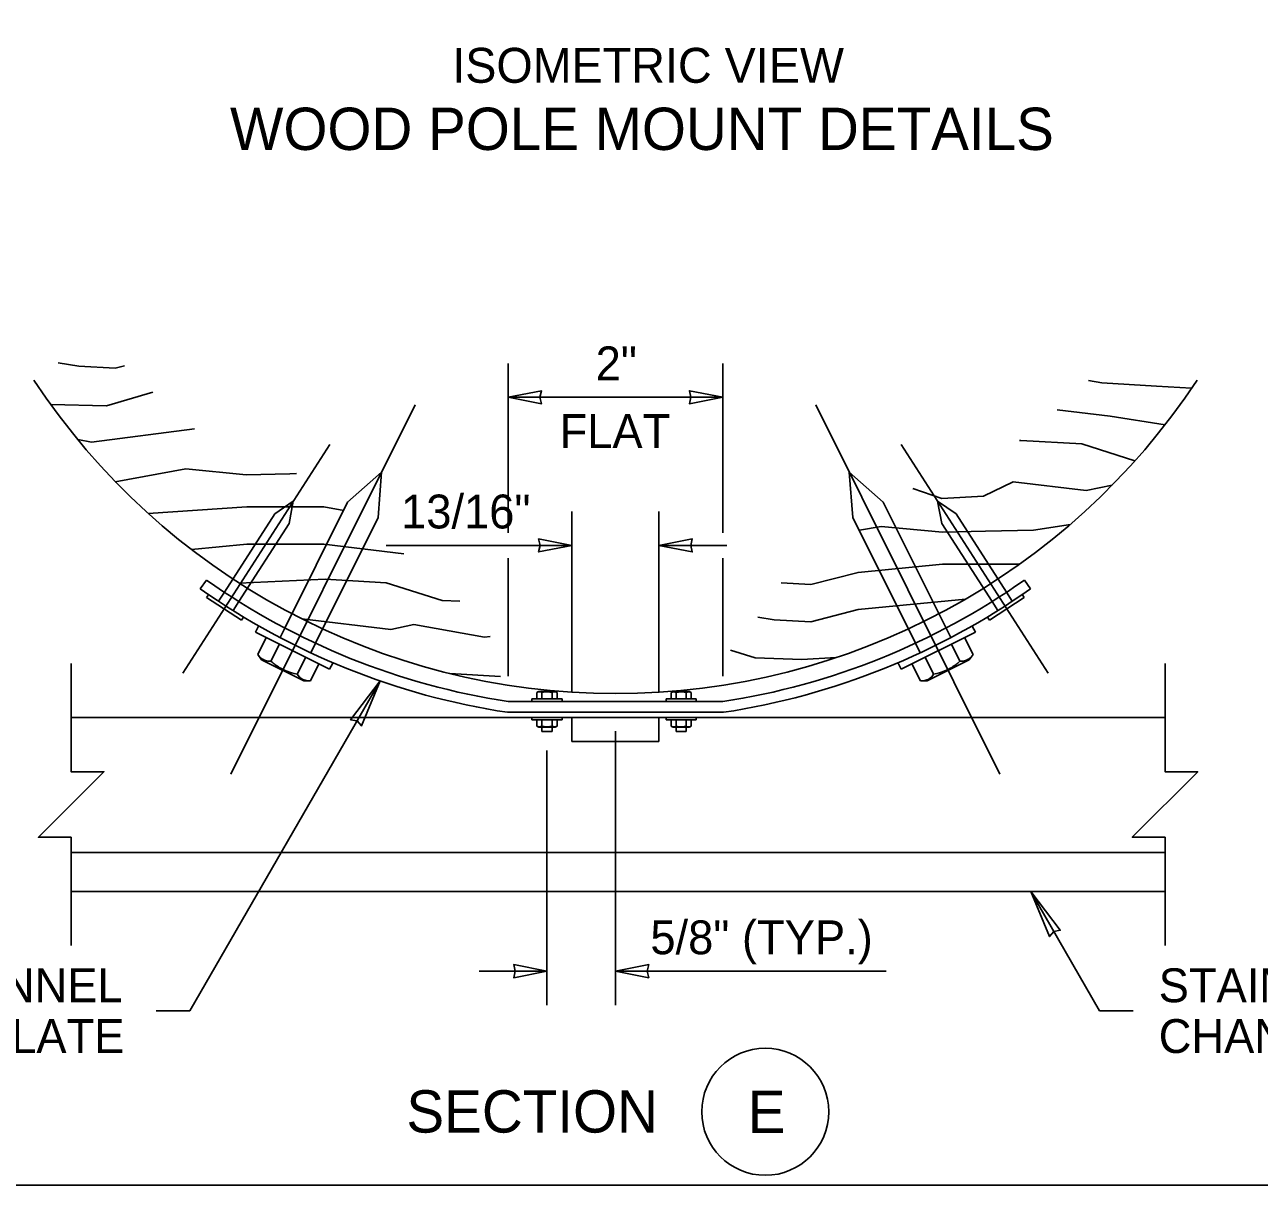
# Model space of a CAD drawing. Extents: x 99862 to 103680, y 99470 to 102076.
# Drawn here: x 101174 to 101757, y 100000 to 100548 of the extents above; entities that cross this region are included whole.
import ezdxf

# ---------------------------------------------------------------- set-up
doc = ezdxf.new("R2010")
doc.units = 0
for name, color, linetype in [('Level 1', 7, 'Continuous'), ('Level 10', 7, 'Continuous'), ('Level 11', 7, 'Continuous'), ('Level 13', 7, 'Continuous'), ('Level 15', 7, 'Continuous'), ('Level 20', 7, 'Continuous'), ('Level 4', 7, 'Continuous'), ('Level 5', 7, 'Continuous'), ('Level 8', 7, 'Continuous')]:
    doc.layers.add(name, color=color, linetype=linetype)

msp = doc.modelspace()

# ---------------------------------------------------------------- linework, layer by layer
at = {"layer": 'Level 1'}
for p, q in [((101195.48, 100220.55), (101712.39, 100220.55)), ((101195.48, 100156.74), (101712.4, 100156.74)), ((101195.48, 100138.29), (101712.39, 100138.29))]:
    msp.add_line(p, q, dxfattribs=at)
msp.add_lwpolyline([(99862, 99999.5), (103151, 99999.5), (103151, 102075.5), (99862, 102075.5)], close=True, dxfattribs=at)
at = {"layer": 'Level 10'}
msp.add_arc((101452.69, 100560.9), 329.06, 213.3564, 326.6436, dxfattribs=at)
at = {"layer": 'Level 11'}
for p, q in [((101606.85, 100323.95), (101593.14, 100328.64)), ((101278.49, 100302.43), (101252.27, 100299.92)), ((101643.63, 100292.9), (101607.16, 100292.9))]:
    msp.add_line(p, q, dxfattribs=at)
for points in [[(101220.68, 100386.7), (101216.33, 100385.58), (101199.07, 100386.54), (101189.36, 100388.09)], [(101724.96, 100376.09), (101708.44, 100377.01), (101682.49, 100378.65), (101676.19, 100379.78)], [(101185.82, 100368.4), (101212.16, 100367.7), (101234.03, 100374.16)], [(101712.38, 100358.8), (101686.39, 100362.95), (101661.44, 100365.93)], [(101253.73, 100356.85), (101205.08, 100350.66), (101198.6, 100351.82)], [(101643.58, 100351.43), (101644.21, 100351.45), (101673.05, 100349.83), (101698.2, 100341.8)], [(101216.35, 100331.94), (101249.62, 100337.95), (101278.18, 100335.19)], [(101278.18, 100335.19), (101298.89, 100335.72), (101301.93, 100335.79)], [(101687.45, 100330.31), (101675.2, 100327.79), (101640.6, 100331.88), (101626.57, 100325.16), (101606.85, 100323.95)], [(101278.49, 100320.01), (101231.92, 100316.9)], [(101324.3, 100318.32), (101314.89, 100320.01), (101278.49, 100320.01)], [(101607.16, 100308.08), (101578.3, 100310.84), (101567.98, 100308.98)], [(101667.67, 100311.77), (101650.16, 100309.1), (101627.56, 100308.62), (101607.16, 100308.08)], [(101352.65, 100297.92), (101314.89, 100302.43), (101278.49, 100302.43)], [(101607.16, 100292.9), (101567.38, 100289.06), (101545.01, 100283.31), (101530.95, 100284.09)], [(101274.83, 100284.05), (101315.53, 100285.82), (101344.37, 100284.2), (101370.75, 100275.78), (101379.1, 100275.47)], [(101618.06, 100276.41), (101567.38, 100271.49), (101545.01, 100265.73), (101527.75, 100266.69), (101520.04, 100267.92)], [(101393.42, 100258.77), (101390.82, 100258.43), (101357.48, 100264.41), (101346.53, 100262.16), (101304.45, 100267.13)], [(101507.05, 100252.4), (101518.73, 100248.67), (101540.83, 100247.85), (101556.98, 100248.8)], [(101398.35, 100239.86), (101374.38, 100241.3)]]:
    msp.add_lwpolyline(points, dxfattribs=at)
at = {"layer": 'Level 13'}
for p, q in [((101256.52, 100281.32), (101259.44, 100285.46)), ((101645.95, 100285.46), (101648.87, 100281.32)), ((101267.94, 100279.66), (101265.17, 100275.42)), ((101637.44, 100279.66), (101640.22, 100275.42)), ((101274.74, 100275.29), (101271.96, 100271.05)), ((101630.65, 100275.29), (101633.43, 100271.05)), ((101296.47, 100262.79), (101294.22, 100258.26)), ((101608.92, 100262.79), (101611.17, 100258.26)), ((101310.95, 100255.64), (101308.68, 100251.08)), ((101594.45, 100255.61), (101596.7, 100251.08)), ((101402.03, 100228.03), (101503.32, 100228.03)), ((101503.75, 100222.97), (101401.64, 100222.97)), ((101432.13, 100220.55), (101432.13, 100209.26)), ((101473.26, 100209.26), (101473.26, 100220.55)), ((101432.13, 100209.26), (101473.26, 100209.26))]:
    msp.add_line(p, q, dxfattribs=at)
for radius, start, end in [(335.39, 234.81571, 261.31091), (335.39, 278.68909, 305.18429), (340.45, 234.81571, 261.37588), (340.45, 278.62412, 305.18429)]:
    msp.add_arc((101452.69, 100559.57), radius, start, end, dxfattribs=at)
at = {"layer": 'Level 15'}
for p, q in [((101402.03, 100307.84), (101402.03, 100387.84)), ((101503.36, 100307.84), (101503.36, 100387.84)), ((101270.97, 100193.69), (101358.04, 100368.18)), ((101402.03, 100371.84), (101503.36, 100371.84)), ((101634.37, 100193.69), (101547.31, 100368.18)), ((101248.2, 100241.47), (101317.66, 100349.52)), ((101657.19, 100241.47), (101587.73, 100349.52)), ((101432.13, 100232.55), (101432.13, 100317.84)), ((101473.26, 100232.55), (101473.26, 100317.84)), ((101432.13, 100301.84), (101344.27, 100301.84)), ((101473.26, 100301.84), (101505.26, 100301.84)), ((101402.03, 100240.03), (101402.03, 100295.84)), ((101503.36, 100240.03), (101503.36, 100295.84)), ((101341.56, 100237.77), (101251.63, 100081.99)), ((101452.69, 100214.04), (101452.69, 100084.66)), ((101420.33, 100204.87), (101420.33, 100084.66)), ((101648.91, 100138.29), (101681.41, 100081.99)), ((101420.33, 100100.66), (101388.33, 100100.66)), ((101452.69, 100100.66), (101580.69, 100100.66)), ((101235.63, 100081.99), (101251.63, 100081.99)), ((101697.41, 100081.99), (101681.41, 100081.99))]:
    msp.add_line(p, q, dxfattribs=at)
for points in [[(101402.03, 100371.84), (101417.75, 100368.76), (101417.02, 100371.84), (101417.75, 100374.93)], [(101503.36, 100371.84), (101487.64, 100368.76), (101488.37, 100371.84), (101487.64, 100374.93)], [(101432.13, 100301.84), (101416.4, 100298.76), (101417.13, 100301.84), (101416.4, 100304.93)], [(101473.26, 100301.84), (101488.99, 100298.76), (101488.26, 100301.84), (101488.99, 100304.93)], [(101341.56, 100237.77), (101327.56, 100219.49), (101330.68, 100218.91), (101332.73, 100216.51)], [(101648.91, 100138.29), (101662.91, 100120.01), (101659.79, 100119.43), (101657.74, 100117.02)], [(101420.33, 100100.66), (101404.61, 100097.58), (101405.34, 100100.66), (101404.61, 100103.75)], [(101452.69, 100100.66), (101468.42, 100097.58), (101467.69, 100100.66), (101468.42, 100103.75)]]:
    msp.add_lwpolyline(points, close=True, dxfattribs=at)
for points in [[(101195.48, 100246.04), (101195.48, 100194.91), (101210.96, 100194.91), (101179.99, 100163.93), (101195.48, 100163.93), (101195.48, 100112.8)], [(101712.39, 100246.04), (101712.39, 100194.91), (101727.88, 100194.91), (101696.91, 100163.93), (101712.39, 100163.93), (101712.39, 100112.8)]]:
    msp.add_lwpolyline(points, dxfattribs=at)
at = {"layer": 'Level 20'}
msp.add_circle((101523.49, 100034.22), 30, dxfattribs=at)
at = {"layer": 'Level 4'}
for p, q in [((101326.1, 100322.25), (101342.2, 100336.44)), ((101342.2, 100336.44), (101340.55, 100315.04)), ((101579.25, 100322.25), (101563.14, 100336.44)), ((101563.14, 100336.44), (101564.8, 100315.04)), ((101291.75, 100316.68), (101300.46, 100322.77)), ((101296.47, 100262.79), (101326.1, 100322.25)), ((101300.46, 100322.77), (101298.48, 100312.22)), ((101608.92, 100262.79), (101579.25, 100322.25)), ((101613.64, 100316.68), (101604.93, 100322.77)), ((101604.93, 100322.77), (101606.91, 100312.22)), ((101267.94, 100279.66), (101291.75, 100316.68)), ((101340.55, 100315.04), (101310.95, 100255.64)), ((101564.8, 100315.04), (101594.44, 100255.64)), ((101637.44, 100279.66), (101613.64, 100316.68)), ((101298.48, 100312.22), (101274.75, 100275.3)), ((101606.91, 100312.22), (101630.64, 100275.3)), ((101259.48, 100277.14), (101275.96, 100266.55)), ((101629.42, 100266.55), (101645.9, 100277.14)), ((101287.66, 100258.27), (101283.67, 100250.27)), ((101617.68, 100258.27), (101621.67, 100250.27)), ((101283.67, 100250.27), (101285.5, 100247.7)), ((101289.89, 100247.17), (101293.88, 100255.16)), ((101615.5, 100247.17), (101611.51, 100255.16)), ((101621.67, 100250.27), (101619.85, 100247.7)), ((101285.5, 100247.7), (101305.39, 100237.77)), ((101302.33, 100240.96), (101306.32, 100248.96)), ((101308.54, 100237.86), (101312.53, 100245.86)), ((101596.8, 100237.86), (101592.81, 100245.86)), ((101603.06, 100240.96), (101599.07, 100248.96)), ((101619.85, 100247.7), (101599.95, 100237.77)), ((101305.39, 100237.77), (101308.54, 100237.86)), ((101599.95, 100237.77), (101596.8, 100237.86))]:
    msp.add_line(p, q, dxfattribs=at)
for points in [[(101260.37, 100278.53), (101259.48, 100277.14)], [(101645.9, 100277.14), (101645.01, 100278.53)], [(101275.96, 100266.55), (101276.85, 100267.93)], [(101628.54, 100267.93), (101629.42, 100266.55)]]:
    msp.add_lwpolyline(points, dxfattribs=at)
for points in [[(101289.89, 100247.17), (101288.6, 100247.13), (101287.39, 100247.3), (101285.28, 100248.36), (101284.42, 100249.22), (101283.67, 100250.27)], [(101621.71, 100250.27), (101620.97, 100249.22), (101620.11, 100248.36), (101618, 100247.3), (101616.79, 100247.13), (101615.5, 100247.17)], [(101302.33, 100240.96), (101300.02, 100241.43), (101297.76, 100242.13), (101294.61, 100243.7), (101293.59, 100244.32), (101291.67, 100245.66), (101290.76, 100246.4), (101289.89, 100247.17)], [(101615.5, 100247.17), (101614.62, 100246.4), (101613.72, 100245.66), (101611.8, 100244.32), (101610.78, 100243.7), (101607.63, 100242.13), (101605.37, 100241.43), (101603.06, 100240.96)], [(101308.54, 100237.86), (101307.25, 100237.82), (101306.04, 100238), (101303.93, 100239.05), (101303.07, 100239.91), (101302.33, 100240.96)], [(101603.06, 100240.96), (101602.32, 100239.91), (101601.46, 100239.05), (101599.35, 100238), (101598.14, 100237.82), (101596.84, 100237.86)]]:
    msp.add_open_spline(points, degree=3, dxfattribs=at)
at = {"layer": 'Level 5'}
for p, q in [((101317.63, 100243.31), (101282.57, 100260.81)), ((101622.78, 100260.81), (101587.72, 100243.31))]:
    msp.add_line(p, q, dxfattribs=at)
for points in [[(101282.57, 100260.81), (101284.04, 100263.75)], [(101621.31, 100263.75), (101622.78, 100260.81)], [(101319.1, 100246.26), (101317.63, 100243.31)], [(101587.72, 100243.31), (101586.25, 100246.26)]]:
    msp.add_lwpolyline(points, dxfattribs=at)
at = {"layer": 'Level 8'}
for p, q in [((101416.54, 100232.87), (101415.59, 100232.36)), ((101415.59, 100232.36), (101415.59, 100229.31)), ((101424.13, 100232.87), (101416.54, 100232.87)), ((101417.96, 100232.36), (101417.96, 100229.31)), ((101422.71, 100232.36), (101422.71, 100229.31)), ((101425.08, 100232.36), (101424.13, 100232.87)), ((101425.08, 100229.31), (101425.08, 100232.36)), ((101479, 100232.34), (101479.95, 100232.85)), ((101479, 100229.29), (101479, 100232.34)), ((101479.95, 100232.85), (101487.54, 100232.85)), ((101481.37, 100232.34), (101481.37, 100229.29)), ((101486.12, 100232.34), (101486.12, 100229.29)), ((101487.54, 100232.85), (101488.49, 100232.34)), ((101488.49, 100232.34), (101488.49, 100229.29)), ((101427.45, 100229.31), (101413.22, 100229.31)), ((101413.22, 100229.31), (101413.22, 100228.12)), ((101427.45, 100228.12), (101427.45, 100229.31)), ((101490.87, 100229.29), (101476.63, 100229.29)), ((101476.63, 100229.29), (101476.63, 100228.11)), ((101490.87, 100228.11), (101490.87, 100229.29)), ((101413.22, 100220.66), (101413.22, 100219.47)), ((101427.45, 100219.47), (101427.45, 100220.66)), ((101476.63, 100220.55), (101476.63, 100219.45)), ((101490.87, 100219.45), (101490.87, 100220.55)), ((101413.22, 100219.47), (101427.45, 100219.47)), ((101415.59, 100219.47), (101415.59, 100216.42)), ((101415.59, 100216.42), (101416.54, 100215.91)), ((101416.54, 100215.91), (101424.13, 100215.91)), ((101417.96, 100216.42), (101417.96, 100219.47)), ((101417.96, 100213.91), (101417.96, 100215.91)), ((101422.71, 100216.42), (101422.71, 100219.47)), ((101422.71, 100215.91), (101422.71, 100213.91)), ((101424.13, 100215.91), (101425.08, 100216.42)), ((101425.08, 100216.42), (101425.08, 100219.47)), ((101476.63, 100219.45), (101490.87, 100219.45)), ((101479, 100219.45), (101479, 100216.4)), ((101479, 100216.4), (101479.95, 100215.89)), ((101479.95, 100215.89), (101487.54, 100215.89)), ((101481.37, 100216.4), (101481.37, 100219.45)), ((101481.37, 100213.89), (101481.37, 100215.89)), ((101486.12, 100216.4), (101486.12, 100219.45)), ((101486.12, 100215.89), (101486.12, 100213.89)), ((101487.54, 100215.89), (101488.49, 100216.4)), ((101488.49, 100216.4), (101488.49, 100219.45)), ((101422.71, 100213.91), (101417.96, 100213.91)), ((101486.12, 100213.89), (101481.37, 100213.89))]:
    msp.add_line(p, q, dxfattribs=at)
for points, degree in [([(101415.59, 100232.36), (101415.98, 100232.57), (101416.37, 100232.7), (101417.18, 100232.7), (101417.57, 100232.57), (101417.96, 100232.36)], 3), ([(101415.59, 100232.36), (101415.59, 100232.36), (101415.59, 100232.36), (101415.59, 100232.36)], 2), ([(101417.96, 100232.36), (101418.74, 100232.57), (101419.53, 100232.7), (101420.74, 100232.7), (101421.14, 100232.67), (101421.93, 100232.55), (101422.32, 100232.47), (101422.71, 100232.36)], 3), ([(101422.71, 100232.36), (101423.1, 100232.57), (101423.49, 100232.7), (101424.3, 100232.7), (101424.69, 100232.57), (101425.08, 100232.36)], 3), ([(101425.08, 100232.36), (101425.08, 100232.36), (101425.08, 100232.36), (101425.08, 100232.36)], 2), ([(101481.37, 100232.34), (101480.98, 100232.55), (101480.59, 100232.68), (101479.79, 100232.69), (101479.39, 100232.55), (101479, 100232.34)], 3), ([(101479, 100232.34), (101479, 100232.34), (101479, 100232.34), (101479, 100232.34)], 2), ([(101486.12, 100232.34), (101485.73, 100232.45), (101485.35, 100232.53), (101484.55, 100232.65), (101484.15, 100232.69), (101482.95, 100232.69), (101482.15, 100232.55), (101481.37, 100232.34)], 3), ([(101488.49, 100232.34), (101488.1, 100232.55), (101487.71, 100232.68), (101486.9, 100232.69), (101486.51, 100232.55), (101486.12, 100232.34)], 3), ([(101488.49, 100232.34), (101488.49, 100232.34), (101488.49, 100232.34), (101488.49, 100232.34)], 2), ([(101415.59, 100216.42), (101415.98, 100216.21), (101416.37, 100216.08), (101417.18, 100216.08), (101417.57, 100216.21), (101417.96, 100216.42)], 3), ([(101417.96, 100216.42), (101418.74, 100216.21), (101419.53, 100216.08), (101420.74, 100216.08), (101421.14, 100216.11), (101421.93, 100216.23), (101422.32, 100216.32), (101422.71, 100216.42)], 3), ([(101422.71, 100216.42), (101423.1, 100216.21), (101423.49, 100216.08), (101424.3, 100216.08), (101424.69, 100216.21), (101425.08, 100216.42)], 3), ([(101479, 100216.4), (101479.39, 100216.19), (101479.79, 100216.06), (101480.59, 100216.06), (101480.98, 100216.19), (101481.37, 100216.4)], 3), ([(101481.37, 100216.4), (101482.15, 100216.19), (101482.95, 100216.06), (101484.15, 100216.06), (101484.55, 100216.09), (101485.35, 100216.21), (101485.73, 100216.3), (101486.12, 100216.4)], 3), ([(101486.12, 100216.4), (101486.51, 100216.19), (101486.9, 100216.06), (101487.71, 100216.06), (101488.1, 100216.19), (101488.49, 100216.4)], 3)]:
    msp.add_open_spline(points, degree=degree, dxfattribs=at)

# ---------------------------------------------------------------- texts
at = {"layer": 'Level 20'}
for s, height, p in [('ISOMETRIC VIEW', 16.5, (101375.58, 100520.4)), ('WOOD POLE MOUNT DETAILS', 20, (101270.54, 100488.65)), ('2"', 16, (101443.33, 100379.84)), ('FLAT', 16, (101426.28, 100347.84)), ('13/16"', 16, (101351.4, 100309.84)), ('SLOTTED CHANNEL', 16, (101012.93, 100086)), ('MOUNTING PLATE', 16, (101030.45, 100062)), ('SECTION', 20, (101353.89, 100024.4)), ('E', 20, (101515.19, 100024.22))]:
    msp.add_text(s, height=height, dxfattribs=at).set_placement(p)
for s, p in [('5/8" (TYP.)', (101469.19, 100108.66)), ('STAINLESS STEEL', (101709.41, 100086)), ('CHANNEL', (101709.41, 100062))]:
    msp.add_text(s, height=16, rotation=360, dxfattribs=at).set_placement(p)

doc.saveas('drawing.dxf')
